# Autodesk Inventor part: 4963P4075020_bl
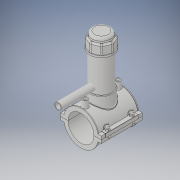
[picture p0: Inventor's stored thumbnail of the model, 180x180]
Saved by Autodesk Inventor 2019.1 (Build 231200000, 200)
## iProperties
Created: 2017-07
Part Number: 4963P4075020_bl
Material: Generic
Document SubType Name: Modeling
Designer: KIM
Density: 1 g/cm^3
Appearance: Default
Author: KIM
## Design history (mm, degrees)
derived "4963P4.ipt"
feature "Solid1::4963P4.ipt" dims "ScaleForDerivedMember" = 10
feature "Solid2::4963P4.ipt" dims "ScaleForDerivedMember" = 10
feature "Solid3::4963P4.ipt" dims "ScaleForDerivedMember" = 10
tag "TaggingFeature1"
body "Solid1"
body "Solid2"
body "Solid3"
other parameters: "d0" = 75 [user parameter], "d2" = 117 [user parameter], "d3" = 18.75 [user parameter], "d4" = 118 [user parameter], "d5" = 0 [user parameter], "d6" = 0.1 [user parameter], "d8" = 0 [user parameter], "d19" = 6 [user parameter], "d20" = 6 [user parameter], "d21" = 70.8 [user parameter], "d23" = 0 [user parameter], "d24" = 35.4 [user parameter], "d26" = 0 [user parameter], "d27" = 3 [user parameter], "d28" = 3 [user parameter], "d29" = 3 [user parameter], "d30" = 25 [user parameter], "d31" = 6 [user parameter], "d32" = 0 [user parameter], "d33" = 0 [user parameter], "d34" = 0.6 [user parameter], "d40" = 50.7 [user parameter], "d41" = 67.5 [user parameter], "d43" = 0 [user parameter], "d45" = 0 [user parameter], "d47" = 119.55 [user parameter], "d70" = 15 [user parameter], "d72" = 0 [user parameter], "d73" = 6 [user parameter], "d75" = 5 [user parameter], "d76" = 0 [user parameter], "d77" = 3.75 [user parameter], "d78" = 67.5 [user parameter], "d79" = 15 [user parameter], "d80" = 47.2 [user parameter], "d82" = 5 deg [user parameter], "d84" = 4 [user parameter], "d85" = 14 [user parameter], "d86" = 0 [user parameter], "d87" = 3 [user parameter], "d88" = 0 [user parameter], "d89" = 1 [user parameter], "d90" = 1 [user parameter], "d91" = 94.4 [user parameter], "d92" = 0 [user parameter], "d93" = 0.5 [user parameter], "d94" = 39.47368 [user parameter], "d96" = 99.45 [user parameter], "d97" = 2.36 [user parameter], "d98" = 0 [user parameter], "d102" = 0.75 [user parameter], "d120" = 140 deg [user parameter], "d121" = 24.228 [user parameter], "d122" = 20 deg [user parameter], "d123" = 195 [user parameter], "d124" = 58.5 [user parameter], "d126" = 0 [user parameter], "d143" = 77.25 [user parameter], "d145" = 17.30769 [user parameter], "d149" = 1.125 [user parameter], "d150" = 19.03846 [user parameter], "d153" = 118 [user parameter], "d154" = 0 [user parameter], "d156" = 48.75 [user parameter], "d157" = 160 deg [user parameter], "d159" = 4.5 [user parameter], "d161" = 1.125 [user parameter], "d162" = 70.8 [user parameter], "d163" = 0 [user parameter], "d164" = 37.5 [user parameter], "d167" = 7.5 [user parameter], "d168" = 47.56098 [user parameter], "d170" = 3.75 [user parameter], "d172" = 0 [user parameter], "d173" = 1 [user parameter], "d175" = 37.5 [user parameter], "d176" = 20 deg [user parameter], "d177" = 5.25 [user parameter], "d178" = 22.5 [user parameter], "d180" = 0 [user parameter], "d183" = 9 [user parameter], "d184" = 4.2 [user parameter], "d185" = 38.35 [user parameter], "d186" = 38.35 [user parameter], "d187" = 48.75 [user parameter], "d188" = 6.75 [user parameter], "d189" = 5.25 [user parameter], "d190" = 0 [user parameter], "d191" = 73.125 [user parameter], "d193" = 8 [user parameter], "d194" = 4.13 [user parameter], "d195" = 90 deg [user parameter], "d197" = 0 [user parameter], "d199" = 0 [user parameter], "d200" = 11.25 [user parameter], "d202" = 0 [user parameter], "d203" = 177 [user parameter], "d204" = 64.125 [user parameter], "d205" = 47.25 [user parameter], "d206" = 57.375 [user parameter], "d207" = 132.75 [user parameter], "d208" = 138.06 [user parameter], "d209" = 164.61 [user parameter], "d210" = 58.05 [user parameter], "d211" = 67.5 [user parameter], "d212" = 54 [user parameter], "d213" = 36 [user parameter], "d216" = 0 [user parameter], "d217" = 7.5 [user parameter], "d218" = 7.5 [user parameter], "d219" = 1.5 [user parameter], "d222" = 75 [user parameter], "d224" = 0 [user parameter], "d227" = 16 [user parameter], "d228" = 125 [user parameter], "d230" = 4.5 [user parameter], "d_" = 75 [user parameter], "B_" = 117 [user parameter], "L_" = 118 [user parameter], "d_t" = 6 [user parameter]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
